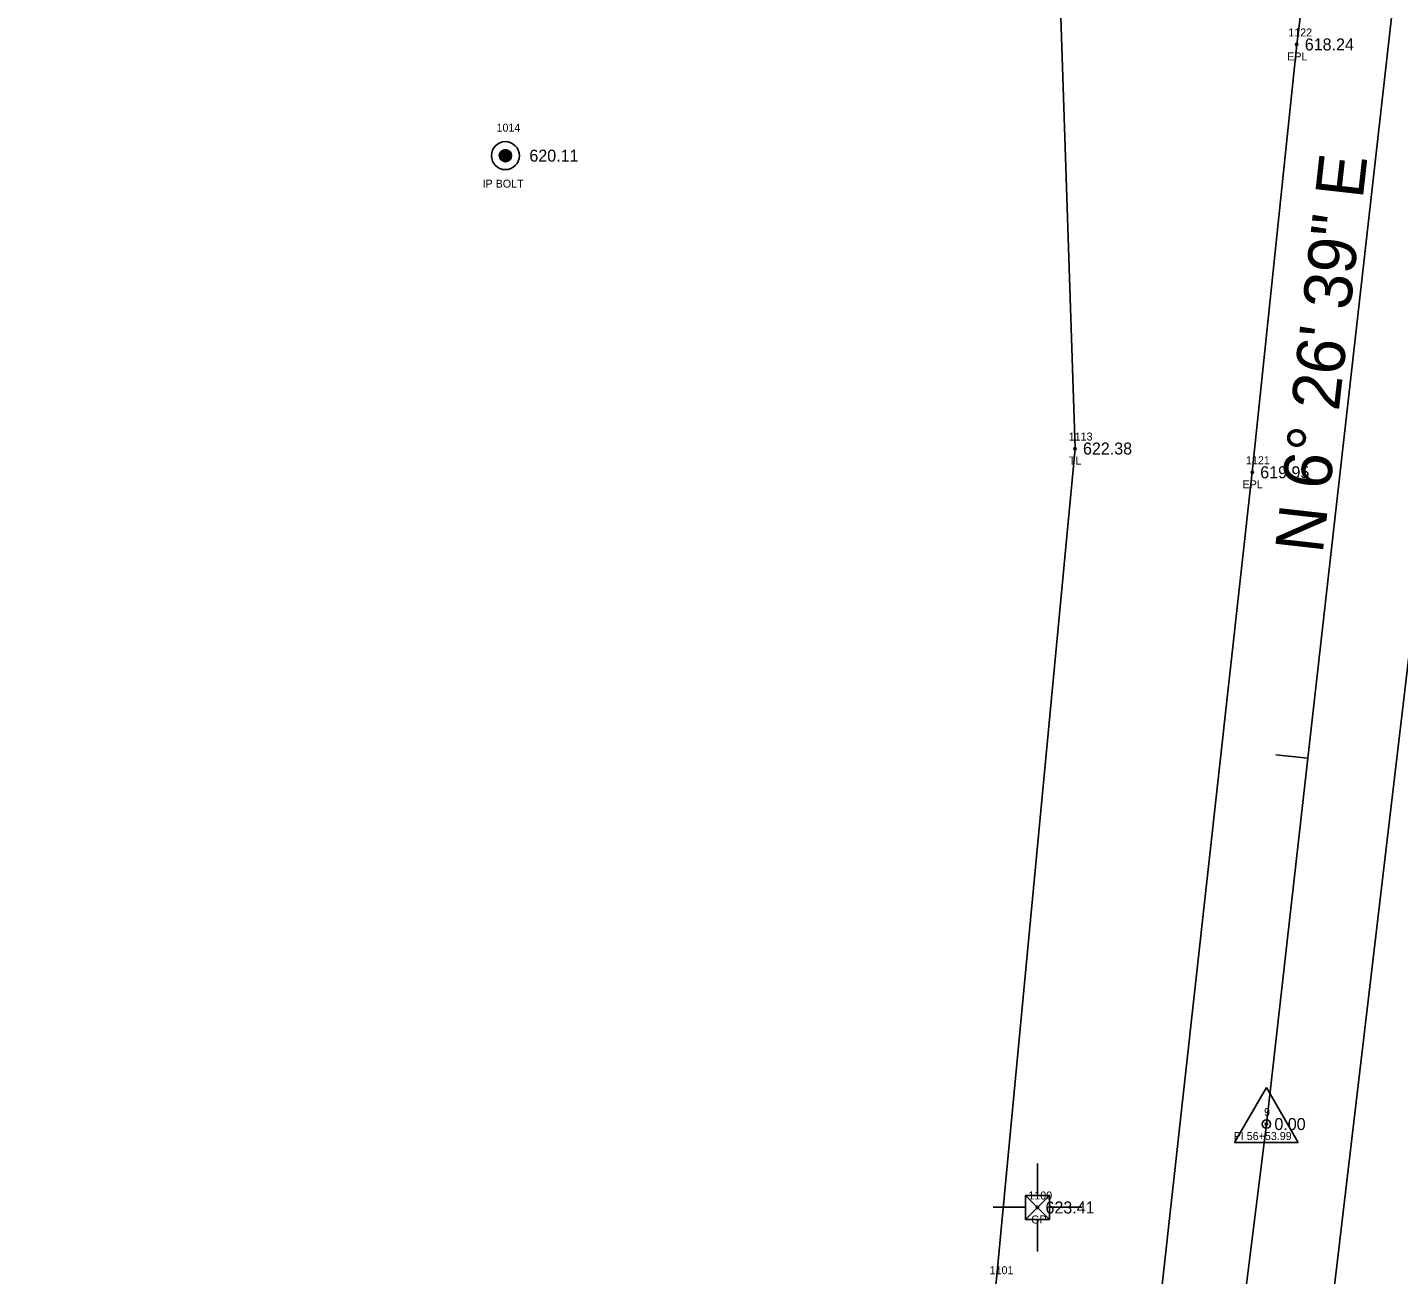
# Model space of a CAD drawing. Extents: x 1694813 to 1696862, y 1086485 to 1091027.
# Drawn here: x 1695755.8 to 1695927.2, y 1087875.5 to 1088031.4 of the extents above; entities that cross this region are included whole.
import ezdxf

# ---------------------------------------------------------------- set-up
doc = ezdxf.new("R2010")
doc.units = 0
for name, color, linetype in [('RD_EX_DV_Prop_txCode', 7, 'Continuous'), ('RD_EX_DV_PropPin', 7, 'Continuous'), ('RD_EX_Road', 7, 'Continuous'), ('RD_EX_Road_txCode', 7, 'Continuous'), ('RD_EX_TX_DV_Prop_ELEV', 7, 'Continuous'), ('RD_EX_TX_Road_ELEV', 7, 'Continuous'), ('RD_EX_TX_UT_ELEV', 7, 'Continuous'), ('RD_EX_TX_VEG_ELEV', 7, 'Continuous'), ('RD_EX_UT', 7, 'Continuous'), ('RD_EX_UT_txCode', 7, 'Continuous'), ('RD_EX_VEG', 7, 'Continuous'), ('RD_EX_VEG_txCode', 7, 'Continuous'), ('RD_HC_Cl', 7, 'Continuous'), ('RD_HC_Data', 7, 'Continuous'), ('RD_HC_Data_Tic', 7, 'Continuous'), ('RD_HC_Survey_ELEV', 7, 'Continuous'), ('RD_HC_txCode', 7, 'Continuous'), ('RD_SMD_Locator', 7, 'Continuous')]:
    doc.layers.add(name, color=color, linetype=linetype)

msp = doc.modelspace()

# ---------------------------------------------------------------- linework, layer by layer
at = {"layer": 'RD_EX_DV_PropPin'}
for p, q in [((1695814.84, 1088015.14), (1695814.84, 1088015.54)), ((1695814.88, 1088015.04), (1695814.88, 1088015.64)), ((1695814.91, 1088014.97), (1695814.91, 1088015.71)), ((1695814.95, 1088014.91), (1695814.95, 1088015.77)), ((1695814.98, 1088014.86), (1695814.98, 1088015.81)), ((1695815.02, 1088014.82), (1695815.02, 1088015.85)), ((1695815.05, 1088014.79), (1695815.05, 1088015.89)), ((1695815.09, 1088014.76), (1695815.09, 1088015.92)), ((1695815.12, 1088014.73), (1695815.12, 1088015.95)), ((1695815.16, 1088014.7), (1695815.16, 1088015.97)), ((1695815.19, 1088014.68), (1695815.19, 1088016)), ((1695815.23, 1088014.66), (1695815.23, 1088016.01)), ((1695815.26, 1088014.65), (1695815.26, 1088016.03)), ((1695815.3, 1088014.63), (1695815.3, 1088016.05)), ((1695815.33, 1088014.62), (1695815.33, 1088016.06)), ((1695815.37, 1088014.61), (1695815.37, 1088016.07)), ((1695815.4, 1088014.6), (1695815.4, 1088016.08)), ((1695815.44, 1088014.59), (1695815.44, 1088016.09)), ((1695815.47, 1088014.59), (1695815.47, 1088016.09)), ((1695815.51, 1088014.58), (1695815.51, 1088016.1)), ((1695815.54, 1088014.58), (1695815.54, 1088016.1)), ((1695815.58, 1088014.58), (1695815.58, 1088016.1)), ((1695815.61, 1088014.58), (1695815.61, 1088016.1)), ((1695815.65, 1088014.58), (1695815.65, 1088016.1)), ((1695815.68, 1088014.59), (1695815.68, 1088016.09)), ((1695815.72, 1088014.59), (1695815.72, 1088016.09)), ((1695815.75, 1088014.6), (1695815.75, 1088016.08)), ((1695815.79, 1088014.61), (1695815.79, 1088016.07)), ((1695815.82, 1088014.62), (1695815.82, 1088016.06)), ((1695815.86, 1088014.63), (1695815.86, 1088016.05)), ((1695815.89, 1088014.65), (1695815.89, 1088016.03)), ((1695815.93, 1088014.66), (1695815.93, 1088016.01)), ((1695815.96, 1088014.68), (1695815.96, 1088016)), ((1695816, 1088014.7), (1695816, 1088015.97)), ((1695816.03, 1088014.73), (1695816.03, 1088015.95)), ((1695816.07, 1088014.76), (1695816.07, 1088015.92)), ((1695816.1, 1088014.79), (1695816.1, 1088015.89)), ((1695816.14, 1088014.82), (1695816.14, 1088015.85)), ((1695816.17, 1088014.86), (1695816.17, 1088015.81)), ((1695816.21, 1088014.91), (1695816.21, 1088015.77)), ((1695816.24, 1088014.97), (1695816.24, 1088015.71)), ((1695816.28, 1088015.04), (1695816.28, 1088015.64)), ((1695816.31, 1088015.14), (1695816.31, 1088015.54))]:
    msp.add_line(p, q, dxfattribs=at)
for radius in [1.75, 0.761]:
    msp.add_circle((1695815.58, 1088015.34), radius, dxfattribs=at)
at = {"layer": 'RD_EX_Road'}
for points in [[(1695879.87, 1087561.29), (1695893.33, 1087665.71), (1695905.96, 1087767.16), (1695918.66, 1087869.54), (1695930.87, 1087972.82), (1695936.26, 1088023.68), (1695942.14, 1088076.32), (1695948.07, 1088128.17), (1695955.04, 1088181.4), (1695962.88, 1088230.72), (1695971.68, 1088284.64), (1695982.02, 1088336.12), (1695993.28, 1088388.48), (1696018.75, 1088494.48), (1696045.23, 1088599.95), (1696055.72, 1088654.41), (1696060.15, 1088705.35), (1696055.83, 1088758.02), (1696044.01, 1088812.16), (1696026.4, 1088860.33), (1696000.41, 1088911.48), (1695972.46, 1088953.82), (1695939.48, 1088998.73), (1695931.21, 1088992.88)], [(1695858.19, 1087564.9), (1695871.71, 1087668.82), (1695884.5, 1087774.69), (1695887.48, 1087794.2), (1695897.57, 1087873.43), (1695908.92, 1087975.76), (1695914.49, 1088029.24), (1695917.65, 1088054.8), (1695920.27, 1088079.09), (1695926.98, 1088130.26), (1695934.75, 1088185.09), (1695942.15, 1088234.62), (1695951.36, 1088288.06), (1695961.48, 1088338.41), (1695972.86, 1088394.13), (1695998.53, 1088499.67), (1696024.81, 1088603.86), (1696034.83, 1088656.78)]]:
    msp.add_lwpolyline(points, dxfattribs=at)
at = {"layer": 'RD_EX_UT'}
for p, q in [((1695882.08, 1087885.36), (1695882.08, 1087889.36)), ((1695883.58, 1087885.36), (1695880.58, 1087882.36)), ((1695880.58, 1087885.36), (1695883.58, 1087882.36)), ((1695883.58, 1087885.36), (1695880.58, 1087885.36)), ((1695880.58, 1087885.36), (1695880.58, 1087882.36)), ((1695883.58, 1087882.36), (1695883.58, 1087885.36)), ((1695880.56, 1087883.9), (1695876.56, 1087883.9)), ((1695883.6, 1087883.92), (1695887.61, 1087883.92)), ((1695880.58, 1087882.36), (1695883.58, 1087882.36)), ((1695882.08, 1087882.36), (1695882.08, 1087878.36))]:
    msp.add_line(p, q, dxfattribs=at)
at = {"layer": 'RD_EX_VEG'}
msp.add_lwpolyline([(1695767.04, 1087738.17), (1695850.84, 1087719.29), (1695876.92, 1087874.52), (1695886.77, 1087978.73), (1695882.04, 1088123.19), (1695966.35, 1088397.22), (1695987.61, 1088500.99), (1696016.82, 1088604.01), (1696023.94, 1088658.84), (1696026.75, 1088706.17), (1696020.44, 1088756.26), (1696012.04, 1088803.02), (1695995.69, 1088847.32), (1695967.16, 1088892.48), (1695790.95, 1089107.47), (1695767.01, 1089177.35), (1695741.24, 1089223.37), (1695720.39, 1089271.33), (1695703.52, 1089329.03), (1695695, 1089381.13)], dxfattribs=at)
at = {"layer": 'RD_HC_Cl'}
for p, q in [((1695910.69, 1087894.29), (1695932.82, 1088090.24)), ((1695866.12, 1087538.58), (1695910.69, 1087894.29))]:
    msp.add_line(p, q, dxfattribs=at)
at = {"layer": 'RD_HC_Data'}
for p, q in [((1695906.71, 1087891.99), (1695910.69, 1087898.87)), ((1695910.69, 1087898.87), (1695914.65, 1087891.99)), ((1695906.71, 1087891.99), (1695914.65, 1087891.99))]:
    msp.add_line(p, q, dxfattribs=at)
msp.add_circle((1695910.69, 1087894.29), 0.529, dxfattribs=at)
at = {"layer": 'RD_HC_Data_Tic'}
msp.add_line((1695915.85, 1087940.01), (1695911.87, 1087940.45), dxfattribs=at)
at = {"layer": 'RD_SMD_Locator'}
for centre in [(1695914.49, 1088029.24), (1695815.58, 1088015.34), (1695886.77, 1087978.73), (1695908.92, 1087975.76), (1695910.69, 1087894.29), (1695882.08, 1087883.86)]:
    msp.add_circle(centre, 0.15, dxfattribs=at)

# ---------------------------------------------------------------- texts
at = {"layer": 'RD_EX_DV_Prop_txCode'}
for s, p in [('1014', (1695814.47, 1088018.34)), ('IP BOLT', (1695812.73, 1088011.34))]:
    msp.add_text(s, height=1, dxfattribs=at).set_placement(p)
at = {"layer": 'RD_EX_Road_txCode'}
for s, p in [('1122', (1695913.43, 1088030.24)), ('EPL', (1695913.29, 1088027.24)), ('1121', (1695908.14, 1087976.76)), ('EPL', (1695907.71, 1087973.76))]:
    msp.add_text(s, height=1, dxfattribs=at).set_placement(p)
at = {"layer": 'RD_EX_TX_DV_Prop_ELEV'}
msp.add_text('620.11', height=1.5, dxfattribs=at).set_placement((1695818.58, 1088014.59))
at = {"layer": 'RD_EX_TX_Road_ELEV'}
for s, p in [('618.24', (1695915.49, 1088028.49)), ('619.95', (1695909.92, 1087975.01))]:
    msp.add_text(s, height=1.5, dxfattribs=at).set_placement(p)
at = {"layer": 'RD_EX_TX_UT_ELEV'}
msp.add_text('623.41', height=1.5, dxfattribs=at).set_placement((1695883.08, 1087883.11))
at = {"layer": 'RD_EX_TX_VEG_ELEV'}
msp.add_text('622.38', height=1.5, dxfattribs=at).set_placement((1695887.77, 1087977.98))
at = {"layer": 'RD_EX_UT_txCode'}
for s, p in [('1100', (1695880.94, 1087884.86)), ('GP', (1695881.3, 1087881.86))]:
    msp.add_text(s, height=1, dxfattribs=at).set_placement(p)
at = {"layer": 'RD_EX_VEG_txCode'}
for s, p in [('1113', (1695885.99, 1087979.73)), ('TL', (1695886, 1087976.73)), ('1101', (1695876.1, 1087875.52))]:
    msp.add_text(s, height=1, dxfattribs=at).set_placement(p)
at = {"layer": 'RD_HC_Data'}
msp.add_text('N 6%%d 26\' 39" E', height=6, rotation=83.5559, dxfattribs=at).set_placement((1695917.72, 1087965.5))
at = {"layer": 'RD_HC_Survey_ELEV'}
msp.add_text('0.00', height=1.5, dxfattribs=at).set_placement((1695911.69, 1087893.54))
at = {"layer": 'RD_HC_txCode'}
for s, p in [('9', (1695910.4, 1087895.29)), ('PI 56+53.99', (1695906.6, 1087892.29))]:
    msp.add_text(s, height=1, dxfattribs=at).set_placement(p)

doc.saveas('drawing.dxf')
